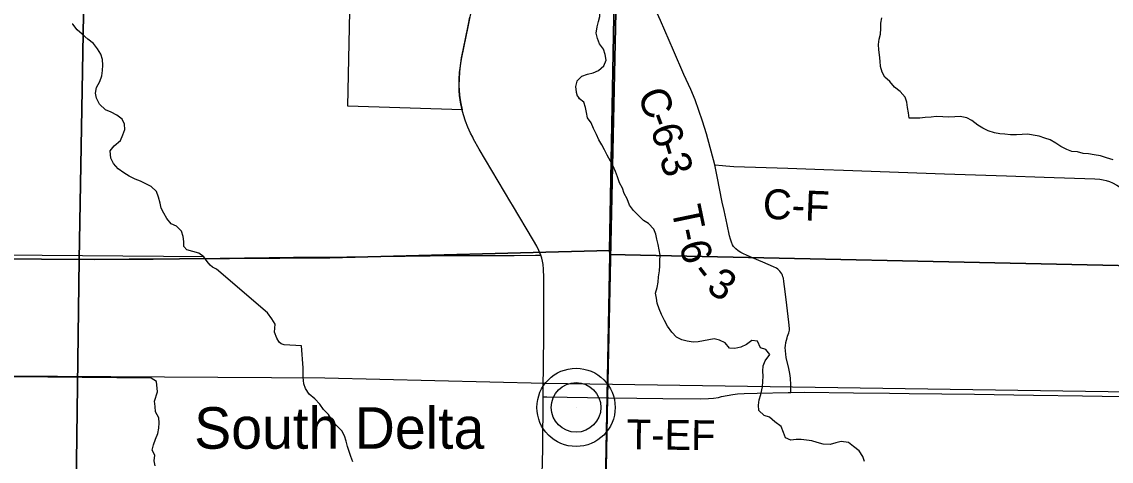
# Model space of a CAD drawing. Extents: x 0 to 42, y 0 to 22.
# Drawn here: x 5.107 to 7.178, y 16.093 to 16.928 of the extents above; entities that cross this region are included whole.
import ezdxf

# ---------------------------------------------------------------- set-up
doc = ezdxf.new("R2010")
doc.units = 0
for name, color, linetype in [('GM_X_Corporation', 7, 'Continuous'), ('GM_X_County_Road', 7, 'Continuous'), ('GM_X_County_Road_Text', 7, 'Continuous'), ('GM_X_Interchange_Ramps', 7, 'Continuous'), ('GM_X_Minor_River', 7, 'Continuous'), ('GM_X_Rail_Line', 7, 'Continuous'), ('GM_X_Section', 7, 'Continuous'), ('GM_X_State_Route', 7, 'Continuous'), ('GM_X_Township_Road', 7, 'Continuous'), ('GM_X_Township_Road_Text', 7, 'Continuous'), ('GM_X_Unincorporated', 7, 'Continuous'), ('GM_X_Unincorporated_Location', 7, 'Continuous'), ('GM_X_Unincorporated_Text', 7, 'Continuous')]:
    doc.layers.add(name, color=color, linetype=linetype)

msp = doc.modelspace()

# ---------------------------------------------------------------- linework, layer by layer
at = {"layer": 'GM_X_Corporation'}
msp.add_lwpolyline([(7.4791, 16.966), (6.494, 16.9822), (6.296, 16.9865), (5.9668, 16.9849), (5.9629, 16.9596), (5.9548, 16.9192), (5.9428, 16.8603), (5.9405, 16.8458), (5.9389, 16.8325), (5.9381, 16.82), (5.9379, 16.8075), (5.9391, 16.7888), (5.9408, 16.7765), (5.9441, 16.7612), (5.7267, 16.7683), (5.7313, 16.9785), (5.223, 16.9761), (5.2286, 17.1938), (5.2302, 17.3226), (4.7322, 17.3283)], dxfattribs=at)
at = {"layer": 'GM_X_County_Road'}
for points in [[(6.4244, 16.6564), (6.4084, 16.7156), (6.4013, 16.7395), (6.3942, 16.76), (6.3871, 16.7801), (6.3787, 16.8), (6.3657, 16.8284), (6.346, 16.8741), (6.3214, 16.9308), (6.3036, 16.9706), (6.2962, 16.9859)], [(6.4244, 16.6564), (6.4392, 16.6551), (6.4453, 16.6544), (6.4608, 16.6536), (6.5632, 16.6504), (6.6315, 16.6479), (6.6688, 16.6464), (6.8613, 16.6398), (6.9792, 16.636), (7.0506, 16.6333), (7.1469, 16.63), (7.1563, 16.6293), (7.1625, 16.6283), (7.1686, 16.6268), (7.1745, 16.6248), (7.1803, 16.6222), (7.1885, 16.6177), (7.2072, 16.6065), (7.2256, 16.595)]]:
    msp.add_lwpolyline(points, dxfattribs=at)
at = {"layer": 'GM_X_Interchange_Ramps'}
for points in [[(6.2063, 15.4779), (6.2205, 16.2146), (6.2391, 17.0939)], [(6.2391, 17.0939), (6.2205, 16.2146), (6.2063, 15.4779)]]:
    msp.add_lwpolyline(points, dxfattribs=at)
at = {"layer": 'GM_X_Minor_River'}
for points in [[(6.1714, 16.8251), (6.1824, 16.8291), (6.1931, 16.8315), (6.2034, 16.8359), (6.2131, 16.8448), (6.2178, 16.8557), (6.2158, 16.866), (6.2129, 16.8763), (6.2052, 16.8867), (6.2016, 16.897), (6.1988, 16.907), (6.2005, 16.9187), (6.2034, 16.9289), (6.2055, 16.9387), (6.2064, 16.9489), (6.2051, 16.9604), (6.192, 16.9686), (6.1807, 16.973), (6.1767, 16.97)], [(5.4151, 16.5014), (5.4149, 16.5109), (5.4136, 16.5204), (5.4104, 16.5304), (5.4012, 16.5401), (5.391, 16.5445), (5.3826, 16.5545), (5.3767, 16.5645), (5.372, 16.5741), (5.37, 16.584), (5.3668, 16.5951), (5.3629, 16.6062), (5.3529, 16.6156), (5.3427, 16.6203), (5.3322, 16.6255), (5.3221, 16.6295), (5.3112, 16.6351), (5.3007, 16.6414), (5.2903, 16.6488), (5.2814, 16.6593), (5.2759, 16.6693), (5.2751, 16.6833), (5.2826, 16.693), (5.2942, 16.7026), (5.2986, 16.7136), (5.3026, 16.7237), (5.3021, 16.7336), (5.2978, 16.7432), (5.2873, 16.751), (5.2765, 16.7569), (5.2659, 16.7613), (5.2548, 16.7722), (5.249, 16.783), (5.2469, 16.7929), (5.2487, 16.8039), (5.2554, 16.8151), (5.2587, 16.826), (5.2605, 16.8362), (5.2607, 16.8461), (5.2602, 16.8567), (5.257, 16.8671), (5.2508, 16.8771), (5.2431, 16.8871), (5.2326, 16.8957), (5.2218, 16.905), (5.2122, 16.9132), (5.2041, 16.9237), (5.2026, 16.9241)], [(7.182, 16.6662), (7.1688, 16.6699), (7.1579, 16.6739), (7.1458, 16.6757), (7.1349, 16.6774), (7.1247, 16.678), (7.1141, 16.6816), (7.1035, 16.6818), (7.0934, 16.6858), (7.0825, 16.6917), (7.0728, 16.698), (7.0623, 16.7043), (7.0517, 16.7072), (7.0408, 16.7112), (7.0299, 16.7133), (7.0193, 16.7146), (7.0087, 16.7145), (6.9977, 16.7136), (6.9867, 16.7134), (6.9761, 16.7151), (6.9663, 16.7157), (6.9561, 16.7174), (6.9444, 16.7215), (6.9343, 16.7266), (6.9246, 16.7321), (6.913, 16.7407), (6.9033, 16.7462), (6.8912, 16.7487), (6.8809, 16.7478), (6.8692, 16.7473), (6.8578, 16.7479), (6.845, 16.7485), (6.8355, 16.7472), (6.8245, 16.7467), (6.8142, 16.7454), (6.7938, 16.745), (6.7924, 16.7553), (6.7907, 16.7656), (6.7894, 16.7755), (6.7866, 16.7854), (6.7766, 16.7959), (6.7658, 16.8044), (6.7572, 16.8148), (6.7476, 16.823), (6.7424, 16.8326), (6.7396, 16.8437), (6.7391, 16.8539), (6.7378, 16.8654), (6.7361, 16.8749), (6.7359, 16.8855), (6.7372, 16.8954), (6.7393, 16.9052), (6.7399, 16.9158), (6.7401, 16.9257), (6.7422, 16.9359)], [(6.1714, 16.8251), (6.1621, 16.8155), (6.1596, 16.8053), (6.1606, 16.7945), (6.1628, 16.788), (6.166, 16.7838)], [(6.4233, 16.3257), (6.413, 16.324), (6.4027, 16.322), (6.3929, 16.3203), (6.383, 16.3197), (6.3721, 16.3214), (6.3619, 16.3243), (6.3517, 16.3291), (6.3425, 16.3387), (6.3344, 16.3499), (6.3285, 16.3607), (6.323, 16.3722), (6.3187, 16.3829), (6.3151, 16.3936), (6.3134, 16.4031), (6.3114, 16.413), (6.3146, 16.4236), (6.3167, 16.4338), (6.3176, 16.4436), (6.319, 16.455), (6.32, 16.4649), (6.3201, 16.4744), (6.3207, 16.485), (6.3187, 16.4953), (6.3166, 16.5052), (6.3141, 16.5151), (6.3124, 16.5246), (6.3085, 16.5342), (6.2984, 16.545), (6.2887, 16.5505), (6.2794, 16.5602), (6.2698, 16.5699), (6.2624, 16.5799), (6.2577, 16.5918), (6.2522, 16.6021), (6.249, 16.6125), (6.2431, 16.6221), (6.2392, 16.6335), (6.2356, 16.6442), (6.2313, 16.6538), (6.2261, 16.6634), (6.2199, 16.6749), (6.2148, 16.6849), (6.2097, 16.6945), (6.2042, 16.7041), (6.1995, 16.7141), (6.1937, 16.7256), (6.1893, 16.7363), (6.1823, 16.7459), (6.1806, 16.7558), (6.1785, 16.7654), (6.1757, 16.7757), (6.1673, 16.7822), (6.166, 16.7838)], [(5.453, 16.482), (4.6837, 16.4882), (4.6837, 16.492), (4.6864, 16.5079), (4.6887, 16.5249), (4.692, 16.5381), (4.6919, 16.5506), (4.6888, 16.5617), (4.6784, 16.5718), (4.6661, 16.5797), (4.6534, 16.5887), (4.6406, 16.5966), (4.6256, 16.6041), (4.6072, 16.6102), (4.5957, 16.6203), (4.5905, 16.6284), (4.5832, 16.6381), (4.5804, 16.6503), (4.5773, 16.664)], [(5.4432, 16.4887), (5.4203, 16.4953), (5.4151, 16.5014)], [(5.6419, 16.2705), (5.6387, 16.3124), (5.6054, 16.3146), (5.5997, 16.3163), (5.596, 16.3194), (5.5916, 16.3271), (5.587, 16.3386), (5.5888, 16.3537), (5.5819, 16.3637), (5.5738, 16.3753), (5.4767, 16.4583), (5.4696, 16.4623), (5.4651, 16.4662), (5.4592, 16.4727), (5.453, 16.482), (5.4432, 16.4887)], [(6.7088, 16.0925), (6.706, 16.1025), (6.6986, 16.1129), (6.6882, 16.1214), (6.6785, 16.1288), (6.6649, 16.1306), (6.6546, 16.1282), (6.6439, 16.125), (6.6307, 16.126), (6.619, 16.1289), (6.6088, 16.1318), (6.5986, 16.1331), (6.5888, 16.1344), (6.579, 16.1343), (6.5687, 16.1333), (6.5586, 16.1377), (6.555, 16.148), (6.5507, 16.1591), (6.5387, 16.1681), (6.5283, 16.1767), (6.5185, 16.1803), (6.5081, 16.1896), (6.5075, 16.1999), (6.5089, 16.2097), (6.5117, 16.2203), (6.515, 16.2347), (6.5156, 16.2449), (6.5166, 16.2551), (6.516, 16.2646), (6.5162, 16.2745), (6.5202, 16.2843), (6.5288, 16.2959), (6.5214, 16.3055), (6.5112, 16.3091), (6.5054, 16.3214), (6.4948, 16.3228), (6.4844, 16.3154), (6.4741, 16.3103), (6.4627, 16.3075), (6.4521, 16.3084), (6.444, 16.3185), (6.4331, 16.3236), (6.4233, 16.3257)], [(5.3527, 16.2512), (4.5012, 16.2596)], [(5.7364, 16.0919), (5.7325, 16.1023), (5.7261, 16.1214), (5.7237, 16.1317), (5.7205, 16.1416), (5.715, 16.1512), (5.705, 16.1609), (5.6961, 16.171), (5.6899, 16.1818), (5.6803, 16.1915), (5.6733, 16.2015), (5.6641, 16.212), (5.6533, 16.2206), (5.6461, 16.2315), (5.6433, 16.2406), (5.6419, 16.2529), (5.6419, 16.2705)], [(5.3602, 16.0844), (5.3582, 16.0943), (5.3596, 16.1045), (5.3549, 16.1141), (5.357, 16.1247), (5.361, 16.1352), (5.3655, 16.1458), (5.3672, 16.1564), (5.3678, 16.1662), (5.3673, 16.1757), (5.3611, 16.1869), (5.3606, 16.1975), (5.3589, 16.2074), (5.3648, 16.2254), (5.363, 16.2445), (5.3527, 16.2512)]]:
    msp.add_lwpolyline(points, dxfattribs=at)
at = {"layer": 'GM_X_Rail_Line'}
msp.add_lwpolyline([(4.4607, 16.2608), (4.6655, 16.258), (5.6831, 16.252), (6.101, 16.2418), (7.4287, 16.222), (8.568, 16.211), (8.9, 16.2074)], dxfattribs=at)
at = {"layer": 'GM_X_Section'}
for points in [[(5.2334, 17.4797), (5.2156, 16.4769), (4.2153, 16.4855), (4.2338, 17.4876)], [(6.2427, 17.4846), (6.224, 16.494), (5.6923, 16.4799), (5.2156, 16.4769), (5.2334, 17.4797)], [(6.2427, 17.4846), (7.2316, 17.475), (7.2205, 16.4649), (6.2249, 16.4863), (6.224, 16.494)], [(6.224, 16.494), (6.2249, 16.4863), (6.2056, 15.4786), (5.2026, 15.4687), (5.2156, 16.4769), (5.6923, 16.4799)], [(4.2153, 16.4855), (5.2156, 16.4769), (5.2026, 15.4687), (4.1963, 15.4797)], [(6.2249, 16.4863), (7.2205, 16.4649), (7.2034, 15.459), (6.2056, 15.4786)]]:
    msp.add_lwpolyline(points, close=True, dxfattribs=at)
at = {"layer": 'GM_X_State_Route'}
for points in [[(5.9443, 16.7607), (5.9435, 16.7637), (5.9411, 16.7759), (5.9393, 16.7883), (5.9385, 16.7976), (5.9381, 16.807), (5.9383, 16.8195), (5.9392, 16.8319), (5.9406, 16.8443), (5.943, 16.8597), (5.9466, 16.878), (5.9555, 16.9206), (5.9589, 16.9374)], [(5.9641, 16.709), (5.9602, 16.7167), (5.955, 16.728), (5.9505, 16.7397), (5.9467, 16.7516), (5.9443, 16.7607)], [(6.0399, 16.5798), (6.0368, 16.5849), (5.9765, 16.6865), (5.9658, 16.7056), (5.9641, 16.709)], [(6.0982, 16.2194), (6.0983, 16.2281), (6.0991, 16.3307), (6.0996, 16.4053), (6.0996, 16.4426), (6.0989, 16.4581), (6.098, 16.4673), (6.097, 16.4734), (6.0955, 16.4793), (6.0936, 16.4849), (6.0899, 16.4937), (6.0858, 16.502), (6.0797, 16.5128), (6.0399, 16.5798)], [(6.0955, 16.0448), (6.0973, 16.1162), (6.0981, 16.2155), (6.0982, 16.2194)]]:
    msp.add_lwpolyline(points, dxfattribs=at)
at = {"layer": 'GM_X_Township_Road'}
for points in [[(6.5691, 16.2242), (6.569, 16.2294), (6.5689, 16.2386), (6.5682, 16.251), (6.567, 16.2602), (6.5653, 16.2693), (6.5603, 16.2905), (6.5592, 16.2967), (6.5585, 16.303), (6.5583, 16.3093), (6.5585, 16.3124), (6.5595, 16.3187), (6.5617, 16.3279), (6.5626, 16.3308), (6.565, 16.3375), (6.5657, 16.3397), (6.5662, 16.3423), (6.5662, 16.3453), (6.5653, 16.3576), (6.5627, 16.3791), (6.5598, 16.4008), (6.557, 16.4256), (6.5559, 16.4348), (6.5548, 16.4409), (6.554, 16.4438), (6.553, 16.4466), (6.5517, 16.4494), (6.5501, 16.452), (6.5483, 16.4544), (6.5463, 16.4565), (6.544, 16.4585), (6.5414, 16.4601), (6.536, 16.4629), (6.516, 16.4714), (6.4959, 16.4799), (6.4791, 16.4875), (6.4739, 16.4902), (6.469, 16.4934), (6.4642, 16.497), (6.4619, 16.4992), (6.4599, 16.5017), (6.4581, 16.5047), (6.456, 16.5094), (6.4541, 16.5152), (6.4525, 16.5215), (6.4479, 16.543), (6.4424, 16.5695), (6.4387, 16.5854), (6.4289, 16.6343), (6.4244, 16.6564)], [(4.5493, 16.4842), (4.5955, 16.4835), (4.757, 16.4818), (4.7943, 16.4814), (4.8657, 16.4805), (5.0676, 16.478), (5.1204, 16.4777), (5.2446, 16.4769), (5.3565, 16.4774), (5.4838, 16.4794), (5.6235, 16.481), (5.6608, 16.4814), (5.7882, 16.4826), (5.931, 16.4842), (6.0428, 16.4844), (6.0832, 16.4848), (6.0936, 16.4849)], [(6.2208, 16.214), (6.223, 16.214), (6.2759, 16.2134), (6.3256, 16.2126), (6.3971, 16.212), (6.4127, 16.2123), (6.4221, 16.213), (6.4313, 16.2146), (6.4374, 16.2161), (6.4586, 16.2199), (6.4678, 16.2211), (6.4802, 16.2219), (6.505, 16.2225), (6.564, 16.2242), (6.5691, 16.2242)], [(6.5691, 16.2242), (6.5951, 16.2245), (6.6884, 16.2234), (6.7567, 16.2227), (6.794, 16.2221), (6.9184, 16.2209), (7.0303, 16.2191), (7.1235, 16.2173), (7.1982, 16.216), (7.2178, 16.216)], [(6.0981, 16.2155), (6.1049, 16.2154), (6.2208, 16.214)]]:
    msp.add_lwpolyline(points, dxfattribs=at)
at = {"layer": 'GM_X_Unincorporated'}
for radius in [0.0744, 0.0472]:
    msp.add_circle((6.1606, 16.1956), radius, dxfattribs=at)
at = {"layer": 'GM_X_Unincorporated_Location'}
msp.add_line((6.1606, 16.1956), (6.1606, 16.1956), dxfattribs=at)

# ---------------------------------------------------------------- texts
at = {"layer": 'GM_X_County_Road_Text'}
for s, height, rotation, p in [('C', 0.0568, 292.7328, (6.2761, 16.7894)), ('-', 0.0568, 290.1212, (6.2939, 16.747)), ('6', 0.0568, 286.9948, (6.3017, 16.7258)), ('-', 0.0568, 286.771, (6.3119, 16.6924)), ('3', 0.0568, 286.7282, (6.3186, 16.6701)), ('C-F', 0.05682, 357.7986, (6.5149, 16.5542))]:
    msp.add_text(s, height=height, rotation=rotation, dxfattribs=at).set_placement(p)
at = {"layer": 'GM_X_Township_Road_Text'}
for s, height, rotation, p in [('T', 0.0568, 281.7125, (6.3413, 16.5737)), ('-', 0.0568, 281.968, (6.35, 16.5318)), ('6', 0.0568, 286.054, (6.3559, 16.5047)), ('-', 0.0568, 307.8468, (6.3762, 16.4502)), ('3', 0.0568, 327.304, (6.4059, 16.4177)), ('T-EF', 0.05682, 359.3573, (6.2567, 16.116))]:
    msp.add_text(s, height=height, rotation=rotation, dxfattribs=at).set_placement(p)
at = {"layer": 'GM_X_Unincorporated_Text'}
msp.add_text('South Delta', height=0.078977, rotation=0, dxfattribs=at).set_placement((5.4345, 16.117))

doc.saveas('drawing.dxf')
